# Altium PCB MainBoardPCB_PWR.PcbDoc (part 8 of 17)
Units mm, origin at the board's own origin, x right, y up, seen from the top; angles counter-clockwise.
Board outline 333.63 x 349.38 mm, 16 copper layers (L1, L2 (GND), L3 (Sign), L4 (GND), L5 (Sign), L6 (PWR/GND), L7(PWR/GND), L8 (PWR/GND), L9 (PWR/GND), L10 (PWR/GND), L11 (PWR/GND), L12 (Sign), L13 (GND), L14 (Sign), L15 (GND), L16), stack 2.503 mm thick; 2187 components, 1615 nets, 7987 pads, 1695 vias.
Unrouted connection lines stored in the file: 4757.
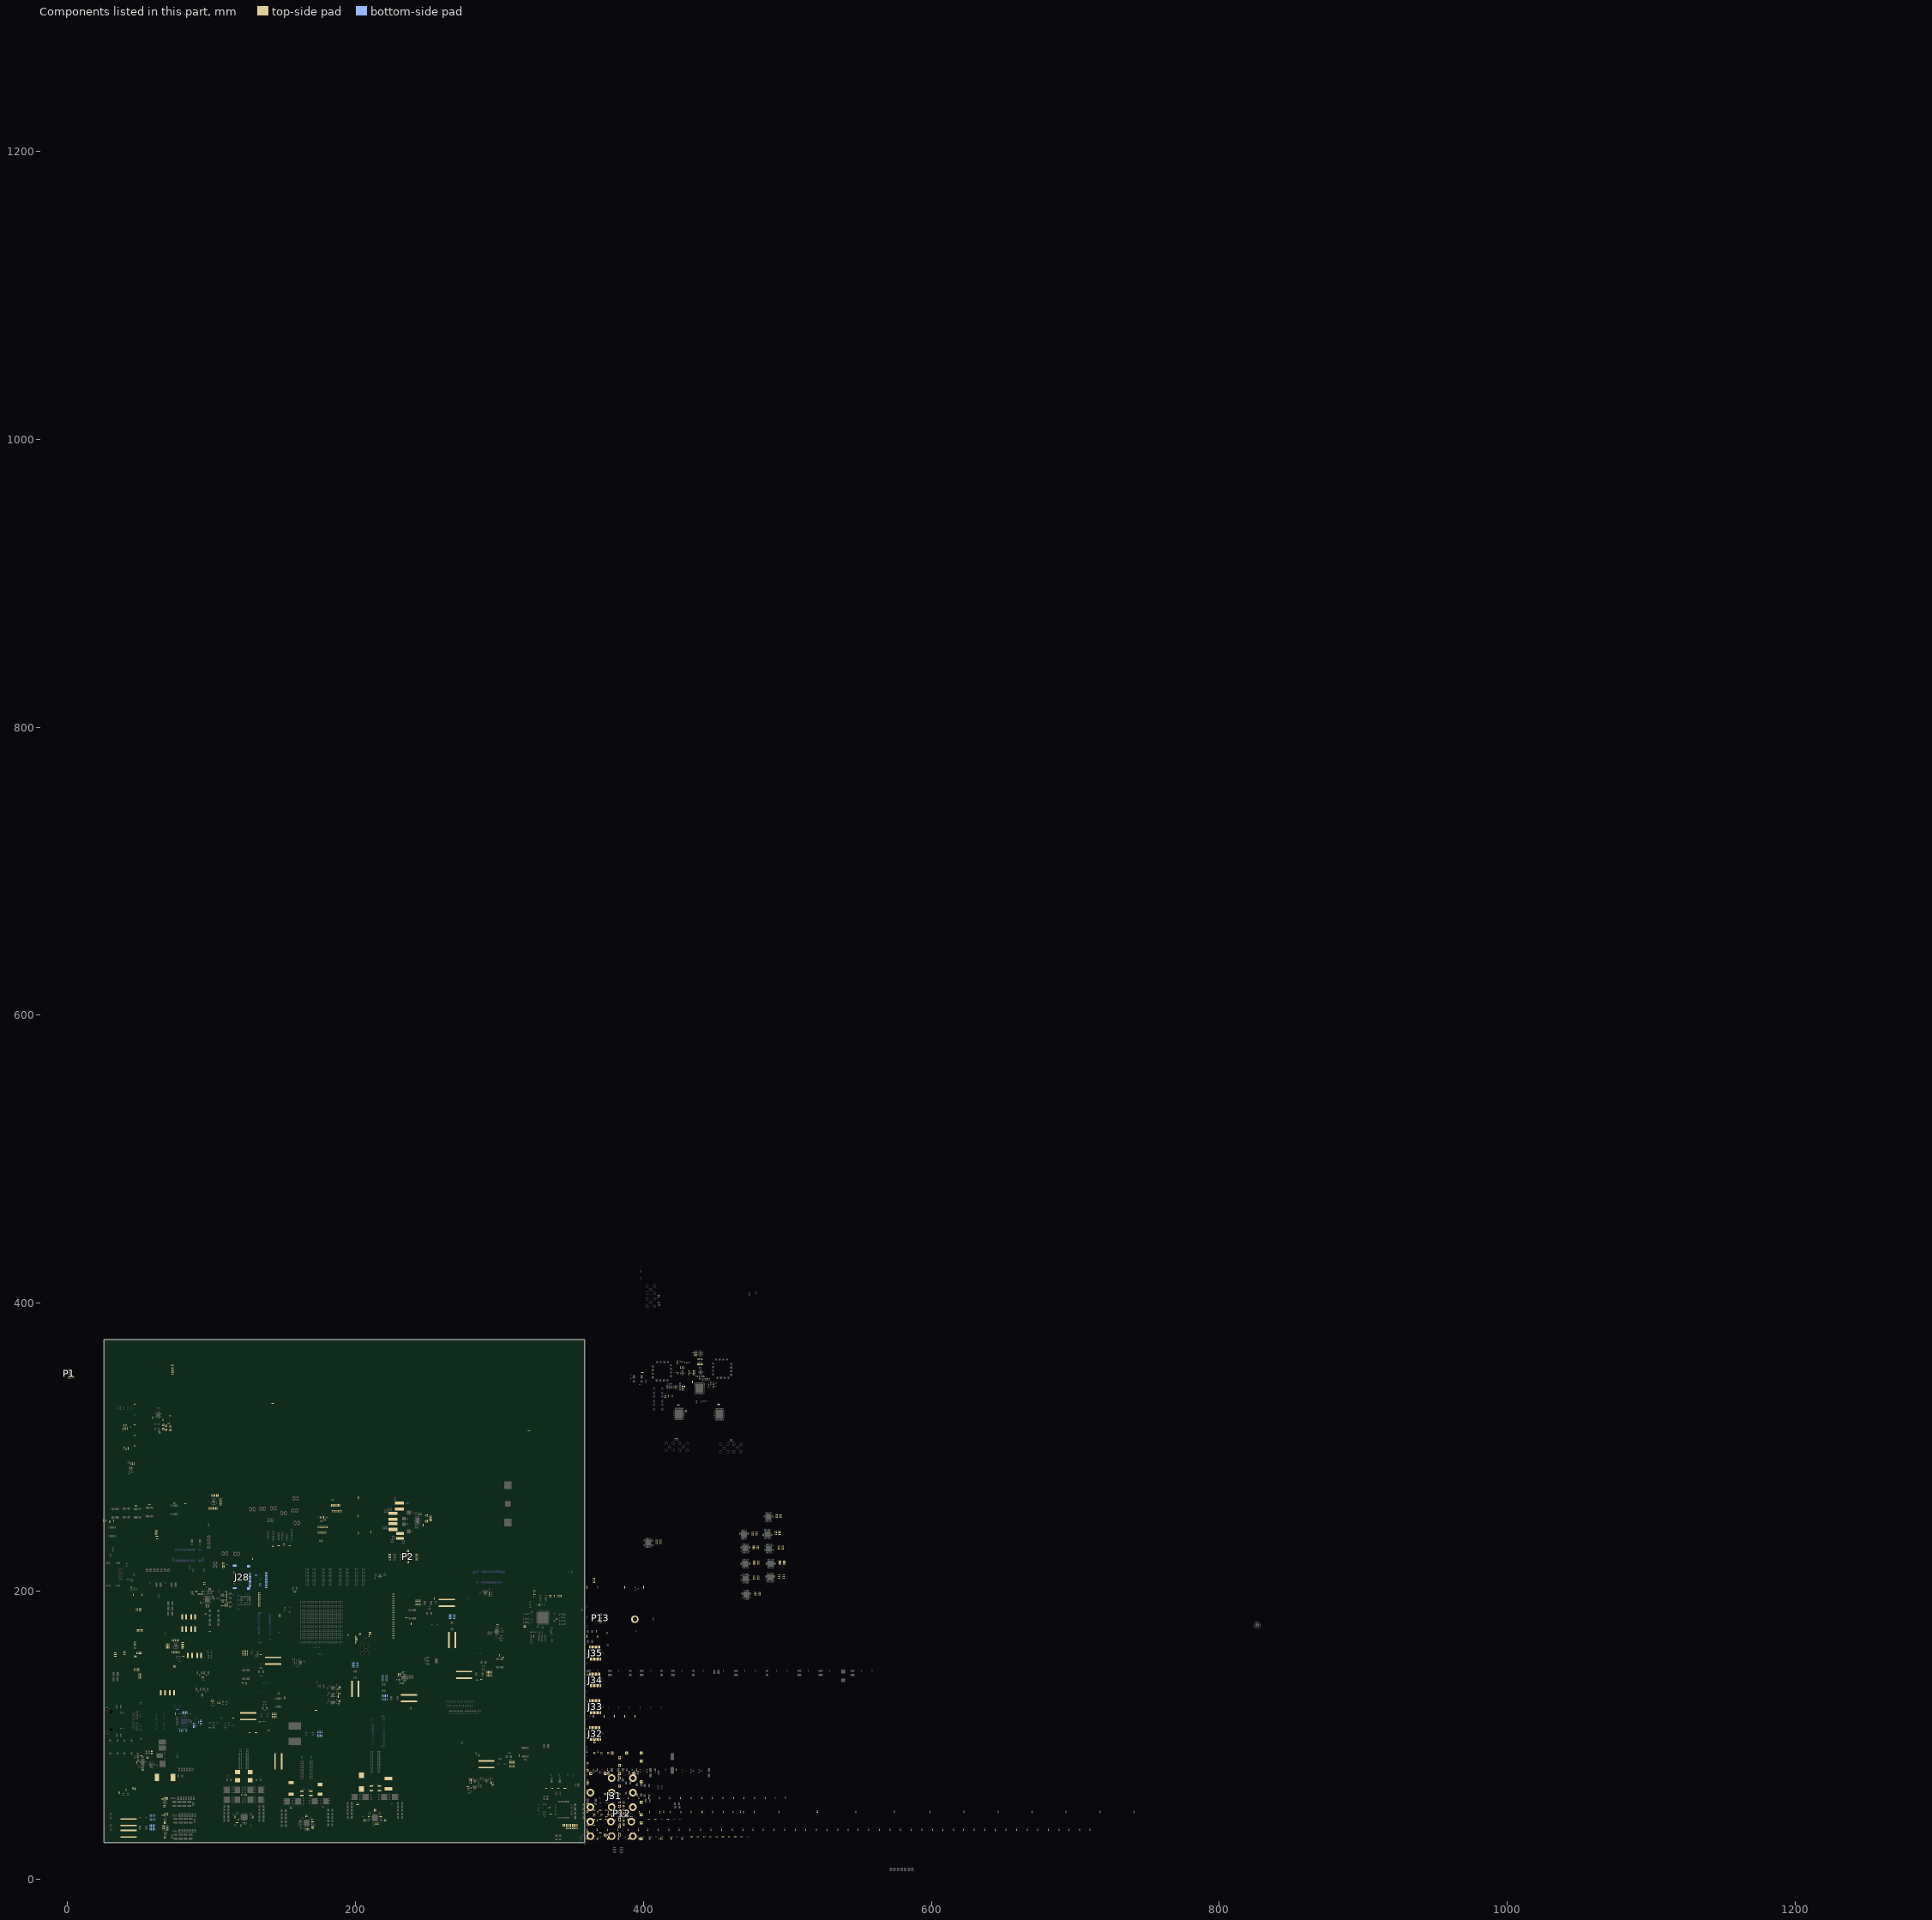
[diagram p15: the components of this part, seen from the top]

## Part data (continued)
J28: "WR-CRD Micro SD Card Connector Push & Push", Contact Resistance=100mOhm, Operating Temperature="-40 to +85degC", Rated Current=0.5A, Withstanding Voltage=500VAC, Working Voltage=30VAC
J31: library part 2007132, Flammability Rating="UL94 V-0", Manufacturer="TE Connectivity", Manufacturer Part Number=2007132-1, Package Quantity=16, Supplier Part Number 1=A97939-ND
J32 J33 J34 J35: "Conn zSFP+ F 20 POS 0.8mm Solder RA SMD 20 Terminal 1 Port zSFP+™ Reel", Current Rating=500mA, Flammability Rating="UL94 V-0", Housing Color=Black, Manufacturer=Molex, Max Operating Temperature=85°C, Max Voltage Rating (AC)=120V, Min Operating Temperature=-40°C, Package Quantity=960, Supplier Part Number 1=WM6178CT-ND
L1 L2 L3 L4 L5 L6 L7 L8: "Ind Power Shielded Wirewound 4.7uH 20% 100KHz Ferrite 1.7A Embossed T/R", Case/Package=Nonstandard, Current Rating=1.7A, DC Resistance (DCR)=84mR, Inductance=4.7uH, Manufacturer="Taiyo Yuden", Max Operating Temperature=125°C, Min Operating Temperature=-40°C, Package Quantity=3500, Ratings=AEC-Q200, Saturation Current=2A, Self Resonant Frequency=35MHz, Supplier Part Number 1=587-3578-1-ND, Test Frequency=100kHz, Tolerance=20%
L9 L10: "220nH Shielded Molded Inductor 25A 1.9mOhm Max Nonstandard", Inductance=220nH@25A, Manufacturer 1=Laird, Supplier Part Number 1=240-3179-1-ND
L11: "1.2µH Shielded Molded Inductor 17A 3.8mOhm Max Nonstandard", Inductance=1.2uH@17A, Manufacturer 1=Laird, Supplier Part Number 1=240-3187-1-ND
L12: "Wurth WE-LHMI Series Shielded Wire-wound SMD Inductor with a Iron Core, 0.68 µH Moulded 14A Idc", Case/Package=Nonstandard, Current Rating=14A, DC Resistance (DCR)=3.99mR, Inductance=680nH, Manufacturer 1="Wurth Electronics", Max Operating Temperature=125°C, Min Operating Temperature=-40°C, Saturation Current=32.5A, Self Resonant Frequency=53MHz, Supplier Part Number 1=732-7217-1-ND, Test Frequency=100kHz, Tolerance=20%
L13 L17: Inductance [µH]=8.2, Part Number=CDRH5D28NP-8R2
L15: library part Inductor, Manufacturer=TDK, Manufacturer Part Number=MLZ1608N6R8LT000, Supplier Part Number 1=445-MLZ1608N6R8LT000CT-ND
L16: Inductance="4.2 µH", Supplier Part Number 1=308-1802-1-ND
L18: "Fixed Inductors 3.3uH 1.57A 30% SMD LP INDUCTOR", Case/Package=Nonstandard, Current Rating=1.57A, DC Resistance (DCR)=49.2mR, Inductance=3.3uH, Manufacturer=Sumida, Max Operating Temperature=100°C, Min Operating Temperature=-40°C, Package Quantity=2000, Supplier Part Number 1=308-2184-1-ND, Test Frequency=100kHz, Tolerance=30%
L19: library part 7843330330, "WE-CHSA SMT High Current Inductor, size 1011, 3.3uH, 13.8A", DC Resistance max.=6.5mOhm, Inductance=3.3uH, Operating Temperature="-55 to +150degC", Rated Current=13.8A, Saturation Current=20.5A, Self Resonant Frequency=55MHz
L20: library part 7443340150, "SMT High Current Cube Inductor WE-HCC, size 8070, 1.5 uH, 16.5 A", DC Resistance max.="5.6 mOhm", Inductance="1.5 uH", Operating Temperature="-40 to +125 degC", Rated Current="16.5 A", Saturation Current="18.5 A", Self Resonant Frequency="120 MHz"
L22: "Inductor Power Shielded Wirewound 22uH 20% 100KHz 20Q-Factor Carbonyl Powder 9A 37mOhm DCR Automotive T/R", Case/Package=Nonstandard, Current Rating=9A, DC Resistance (DCR)=37mR, Inductance=22uH, Inductance Tolerance=20%, Manufacturer=Bourns, Max Operating Temperature=150°C, Min Operating Temperature=-40°C, Ratings=AEC-Q200, Saturation Current=12A, Self Resonant Frequency=6MHz, Supplier Part Number 1=SRP1265A-220MCT-ND, Test Frequency=100kHz
MP1_PCIE0 MP1_PCIE1 MP1_PCIE2 MP1_PCIE3 MP1_PCIE4 MP2_PCIE0 MP2_PCIE1 MP2_PCIE2 MP2_PCIE3 MP2_PCIE4 MP3_PCIE0 MP3_PCIE1 MP3_PCIE2 MP3_PCIE3 MP3_PCIE4: library part 9774025243R, "WA-SMSI SMT Steel Spacer, OD4.35mm, M2x2.5mm", Operating Temperature="-55 to +150degC"
P1 P13: "Header, 3-Pin"
P2: "Header, 4-Pin"
P3 P4 P5 P11: "Header, 2-Pin"
P6: "Male Header, Pitch 2.54 mm, 1 x 2 Position, Height 10.49 mm, Tail Length 3.556 mm, -55 to 105 degC, RoHS, Bulk", Color=White, Current, Rating="5  A", Flammability Rating=UL94V-0, Supplier Part Number 1=A1921-ND, Temperature, Operating="-55 to +105  °C", Voltage, Rating="250  V"
P12: "Header, 7-Pin, Dual row"
R1 R2 R71 R72 R73 R74 R91 R92 R93 R94 R127 R139 R141 R142 R143 R144 R151 R152 R153 R154 R161 R162 R163 R164 R345 R376 R377 R378 R402 R403 R404 R405 R406 R407 R408 R409 R411 R412 R413 R414 R415 R416 R418 R421 R481 R498 R540 R636 R637 R638 R639 R640 R641 R642 R643 R692 R722 R723 R724 R725 R726 R727 R728 R729: library part Resistor, "SMT Resistor", Case Code (Imperial)=0402, Case Code (Metric)=1005, Manufacturer=Vishay, Manufacturer Part Number=CRCW04020000Z0ED, Max Operating Temperature=155°C, Max Power Dissipation=63mW, Min Operating Temperature=-55°C, Package Quantity=1, Resistance=0mR, Supplier Part Number 1=541-0.0JCT-ND, Temperature Coefficient=100ppm/°C, Tolerance=5%, Voltage Rating=50V
R3_I2C_Bridge R3_I2C_Bridge_2 R3_I2C_Bridge_3 R4_I2C_Bridge R4_I2C_Bridge_2 R4_I2C_Bridge_3 R5_I2C_Bridge R5_I2C_Bridge_2 R5_I2C_Bridge_3 R6_I2C_Bridge R6_I2C_Bridge_2 R6_I2C_Bridge_3 R7_I2C_Bridge R7_I2C_Bridge_2 R7_I2C_Bridge_3 R8_I2C_Bridge R8_I2C_Bridge_2 R8_I2C_Bridge_3 R9_I2C_Bridge R9_I2C_Bridge_2 R9_I2C_Bridge_3 R10_I2C_Bridge R10_I2C_Bridge_2 R10_I2C_Bridge_3 R106 R109 R124 R223_I2C_Bridge R223_I2C_Bridge_2 R223_I2C_Bridge_3 R224_I2C_Bridge R224_I2C_Bridge_2 R224_I2C_Bridge_3 R225_I2C_Bridge R225_I2C_Bridge_2 R225_I2C_Bridge_3 R226_I2C_Bridge R226_I2C_Bridge_2 R226_I2C_Bridge_3 R227_I2C_Bridge R227_I2C_Bridge_2 R227_I2C_Bridge_3 R231_SPI_bridge2 R232_SPI_bridge1 R232_SPI_bridge2 R232_SPI_bridge3 R233_SPI_bridge2 R234_SPI_bridge1 R234_SPI_bridge2 R234_SPI_bridge3 R235_SPI_bridge1 R235_SPI_bridge2 R235_SPI_bridge3 R236_SPI_bridge2 R237_SPI_bridge1 R237_SPI_bridge2 R237_SPI_bridge3 R238_SPI_bridge2 R239_SPI_bridge1 R239_SPI_bridge2 R239_SPI_bridge3 R240_SPI_bridge2 R424 R428 R488 R499 R544 R558_I2C_Bridge R558_I2C_Bridge_2 R558_I2C_Bridge_3 R559_I2C_Bridge R559_I2C_Bridge_2 R559_I2C_Bridge_3 R560_I2C_Bridge R560_I2C_Bridge_2 R560_I2C_Bridge_3 R599 R694: library part Resistor, Case Code (Imperial)=0402, Case Code (Metric)=1005, Manufacturer=Panasonic, Manufacturer Part Number=ERJ-2RKF1001X, Max Operating Temperature=155°C, Max Power Dissipation=100mW, Min Operating Temperature=-55°C, Package Quantity=1, Supplier Part Number 1=P1.00KLCT-ND, Temperature Coefficient=100ppm/°C, Tolerance=1%, Voltage Rating=50V
R11 R13 R29 R30 R214 R218 R630: library part Resistor, Case/Package=0402, Case Code (Metric)=1005, Manufacturer 1=Yageo, Manufacturer Part Number 1=RC0402FR-0710KL, Max Operating Temperature=155°C, Min Operating Temperature=-55°C, Power Rating=62.5mW, Supplier Part Number 1=311-10.0KLRCT-ND, Temperature Coefficient=100ppm/°C, Tolerance=1%, Voltage Rating=50V
R12 R15 R17 R20 R677 R678 R679 R680: library part Resistor, Case/Package=0402, Case Code (Metric)=1005, Manufacturer 1=Yageo, Manufacturer Part Number 1=RC0402FR-0795K3L, Max Operating Temperature=155°C, Max Power Dissipation=63mW, Min Operating Temperature=-55°C, Package Quantity=1, Power Rating=62.5mW, Supplier Part Number 1=311-95.3KLRCT-ND, Temperature Coefficient=100ppm/°C, Tolerance=1%, Voltage Rating=50V
R14 R16 R22 R24 R304 R388 R389 R390 R665 R669 R670: library part Resistor, Case/Package=0402, Case Code (Metric)=1005, Manufacturer 1=Yageo, Manufacturer Part Number 1=RC0402JR-070RL, Max Operating Temperature=155°C, Max Power Dissipation=63mW, Min Operating Temperature=-55°C, Package Quantity=1, Power Rating=62.5mW, Supplier Part Number 1=311-0.0JRCT-ND, Temperature Coefficient=200ppm/°C, Tolerance=5%, Voltage Rating=50V
R18 R21 R681: library part Resistor, Case/Package=0402, Case Code (Metric)=1005, Manufacturer="Stackpole Electronics", Manufacturer Part Number=RMCF0402FT24K9, Max Operating Temperature=155°C, Max Power Dissipation=63mW, Min Operating Temperature=-55°C, Supplier Part Number 1=RMCF0402FT24K9CT-ND, Temperature Coefficient=100ppm/°C, Tolerance=1%
R19 R23 R25 R26 R683: library part Resistor, Case/Package=0402, Case Code (Metric)=1005, Manufacturer 1=Yageo, Manufacturer Part Number 1=RC0402FR-074K87L, Max Operating Temperature=155°C, Max Power Dissipation=63mW, Min Operating Temperature=-55°C, Power Rating=62.5mW, Supplier Part Number 1=YAG3175CT-ND, Temperature Coefficient=100ppm/°C, Tolerance=1%, Voltage Rating=50V
R27 R28 R182 R191 R200 R209 R228 R269: library part Resistor, Case/Package=0402, Case Code (Metric)=1005, Manufacturer=Panasonic, Manufacturer Part Number=ERJ-2RKF1021X, Max Operating Temperature=155°C, Max Power Dissipation=100mW, Min Operating Temperature=-55°C, Package Quantity=1, Supplier Part Number 1=P1.02KLCT-ND, Temperature Coefficient=100ppm/°C, Tolerance=1%, Voltage Rating=50V
R31 R32 R33 R34 R35 R36 R37 R38 R39 R40 R41 R42 R43 R44 R45 R46 R47 R48 R49 R50 R51 R53 R55 R57 R59: library part Resistor, Case/Package=0402, Case Code (Metric)=1005, Manufacturer=Panasonic, Manufacturer Part Number=ERJ-2RKF39R2X, Max Operating Temperature=155°C, Max Power Dissipation=100mW, Min Operating Temperature=-55°C, Package Quantity=1, Supplier Part Number 1=P39.2LCT-ND, Temperature Coefficient=100ppm/°C, Tolerance=1%, Voltage Rating=50V
R52 R54: library part Resistor, Case/Package=0402, Case Code (Metric)=1005, Manufacturer=Panasonic, Manufacturer Part Number=ERJ-2RKF36R0X, Max Operating Temperature=155°C, Max Power Dissipation=100mW, Min Operating Temperature=-55°C, Package Quantity=10000, Supplier Part Number 1=P36.0LCT-ND, Temperature Coefficient=100ppm/°C, Tolerance=1%, Voltage Rating=50V
R56: library part Resistor, Case/Package=0402, Case Code (Metric)=1005, Manufacturer=Yageo, Manufacturer Part Number=RC0402FR-07499RL, Max Operating Temperature=155°C, Max Power Dissipation=63mW, Min Operating Temperature=-55°C, Package Quantity=1, Power Rating=62.5mW, Supplier Part Number 1=311-499LRCT-ND, Temperature Coefficient=100ppm/°C, Tolerance=1%, Voltage Rating=50V
R58 R99: library part Resistor, Case/Package=0402, Case Code (Metric)=1005, Manufacturer=Panasonic, Manufacturer Part Number=ERJ-2RKF4701X, Max Operating Temperature=155°C, Max Power Dissipation=100mW, Min Operating Temperature=-55°C, Package Quantity=1, Supplier Part Number 1=P4.70KLCT-ND, Temperature Coefficient=100ppm/°C, Tolerance=1%, Voltage Rating=50V
R60 R231_SPI_bridge1 R231_SPI_bridge3 R233_SPI_bridge1 R233_SPI_bridge3 R236_SPI_bridge1 R236_SPI_bridge3 R238_SPI_bridge1 R238_SPI_bridge3 R240_SPI_bridge1 R240_SPI_bridge3 R252 R253 R254 R255 R427 R538: library part Resistor, Case/Package=0402, Case Code (Metric)=1005, Manufacturer=Panasonic, Manufacturer Part Number=ERJ-2RKF1001X, Max Operating Temperature=155°C, Max Power Dissipation=100mW, Min Operating Temperature=-55°C, Package Quantity=1, Supplier Part Number 1=P1.00KLCT-ND, Temperature Coefficient=100ppm/°C, Tolerance=1%, Voltage Rating=50V
R61 R62 R63 R64: library part Resistor, Case/Package=0402, Case Code (Metric)=1005, Manufacturer=Vishay, Manufacturer Part Number=CRCW0402240RFKED, Max Operating Temperature=155°C, Max Power Dissipation=63mW, Min Operating Temperature=-55°C, Package Quantity=10, Supplier Part Number 1=541-240LCT-ND, Temperature Coefficient=100ppm/°C, Tolerance=1%, Voltage Rating=50V
R65 R66 R67 R68 R83 R84 R85 R86 R97 R98 R123 R135 R136 R137 R138 R145 R146 R147 R148 R155 R156 R157 R158 R276 R346 R347 R348 R349 R350 R351 R352 R353 R354 R355 R356 R357 R363 R364 R365 R367 R381 R382 R425 R426 R730 R731 R732 R733 R734: library part Resistor, Case Code (Imperial)=0402, Case Code (Metric)=1005, Manufacturer=Panasonic, Manufacturer Part Number=ERJ-2RKF4701X, Max Operating Temperature=155°C, Max Power Dissipation=100mW, Min Operating Temperature=-55°C, Package Quantity=1, Supplier Part Number 1=P4.70KLCT-ND, Temperature Coefficient=100ppm/°C, Tolerance=1%, Voltage Rating=50V
R69 R70 R75 R76 R78 R79 R80 R82 R126 R311 R489 R534 R535 R541 R542 R543 R654 R657: library part Resistor, Case Code (Imperial)=0402, Case Code (Metric)=1005, Manufacturer="Vishay Dale", Manufacturer Part Number=CRCW0402100RFKED, Max Operating Temperature=155°C, Max Power Dissipation=63mW, Min Operating Temperature=-55°C, Package Quantity=10, Supplier Part Number 1=541-100LDKR-ND, Temperature Coefficient=100ppm/°C, Tolerance=1%, Voltage Rating=50V
R77: library part Resistor, "RES SMD 7.5K OHM 0.5% 1/16W 0402", Case Code (Imperial)=0402, Case Code (Metric)=1005, Manufacturer=Susumu, Manufacturer Part Number=RR0510P-752-D, Max Operating Temperature=125°C, Max Power Dissipation=63mW, Min Operating Temperature=-55°C, Package Quantity=1, Power Rating=62.5mW, Supplier Part Number 1=RR05P7.5KDCT-ND, Temperature Coefficient=25ppm/°C, Tolerance=0.5%, Voltage Rating=25V, Voltage Rating (DC)=50V
R81 R245 R305 R308 R309: library part Resistor, Case/Package=0402, Case Code (Metric)=1005, Manufacturer="Vishay Dale", Manufacturer Part Number=CRCW0402100RFKED, Max Operating Temperature=155°C, Max Power Dissipation=63mW, Min Operating Temperature=-55°C, Package Quantity=10, Supplier Part Number 1=541-100LDKR-ND, Temperature Coefficient=100ppm/°C, Tolerance=1%, Voltage Rating=50V
R87 R88 R89 R90 R95 R96 R101 R102 R103 R104 R105 R107 R108 R110 R111 R112 R115 R116 R117 R118 R119 R120 R121 R122 R362: library part Resistor, "RES SMD 30 OHM 0.5% 1/16W 0402", Case Code (Imperial)=0402, Case Code (Metric)=1005, Manufacturer=Panasonic, Manufacturer Part Number=ERA-2AKD300X, Max Operating Temperature=155°C, Max Power Dissipation=63mW, Min Operating Temperature=-55°C, Package Quantity=10000, Power Rating=62.5mW, Supplier Part Number 1=P30DDCT-ND, Temperature Coefficient=100ppm/°C, Tolerance=0.5%
R100 R292 R629: library part Resistor
R113: library part Resistor, "Thick Film Resistors 34.8K OHM 1%", Case Code (Imperial)=0402, Case Code (Metric)=1005, Manufacturer=Yageo, Manufacturer Part Number=RC0402FR-0734K8L, Max Operating Temperature=155°C, Max Power Dissipation=63mW, Min Operating Temperature=-55°C, Power Rating=62.5mW, Supplier Part Number 1=YAG3125CT-ND, Temperature Coefficient=100ppm/°C, Tolerance=1%, Voltage Rating=50V
R114 R274 R340 R343 R395 R398 R506 R507 R514 R515 R522 R523 R530 R531 R546 R547 R548 R549 R550 R551 R552 R553 R554 R555 R556 R557 R618 R659 R660 R661 R662 R663 R664 R688 R735 R744 R817 R818 R819 R820 R821 R822 R823 R824 R833 R834 R836 R837 R839: library part Resistor, Case Code (Imperial)=0402, Case Code (Metric)=1005, Manufacturer 1=Yageo, Manufacturer Part Number 1=RC0402FR-0710KL, Max Operating Temperature=155°C, Min Operating Temperature=-55°C, Power Rating=62.5mW, Supplier Part Number 1=311-10.0KLRCT-ND, Temperature Coefficient=100ppm/°C, Tolerance=1%, Voltage Rating=50V
R125 R128 R129: library part Resistor, "SMT Resistor", Case/Package=0402, Case Code (Metric)=1005, Manufacturer=Panasonic, Manufacturer Part Number=ERJ-2RKF1002X, Max Operating Temperature=155°C, Max Power Dissipation=100mW, Min Operating Temperature=-55°C, Package Quantity=1, Supplier Part Number 1=P10.0KLCT-ND, Temperature Coefficient=100ppm/°C, Tolerance=1%, Voltage Rating=50V
R130 R131 R132 R133 R134: library part Resistor, "SMT Resistor", Case/Package=0402, Case Code (Metric)=1005, Manufacturer=Vishay, Manufacturer Part Number=CRCW04020000Z0ED, Max Operating Temperature=155°C, Max Power Dissipation=63mW, Min Operating Temperature=-55°C, Package Quantity=1, Resistance=0mR, Supplier Part Number 1=541-0.0JCT-ND, Temperature Coefficient=100ppm/°C, Tolerance=5%, Voltage Rating=50V
R140: library part Resistor, "RES SMD 2.2 OHM 5% 1/16W 0402", Case Code (Imperial)=0402, Case Code (Metric)=1005, Manufacturer=Yageo, Manufacturer Part Number=RC0402JR-072R2L, Max Operating Temperature=155°C, Max Power Dissipation=63mW, Min Operating Temperature=-55°C, Package Quantity=1, Power Rating=62.5mW, Supplier Part Number 1=311-2.2JRCT-ND, Temperature Coefficient=200ppm/°C, Tolerance=5%, Voltage Rating=50V
R149: library part Resistor, "Thick Film Resistors - SMD 196K OHM 1%", Case/Package=0402, Case Code (Metric)=1005, Manufacturer=Yageo, Manufacturer Part Number=RC0402FR-07196KL, Max Operating Temperature=155°C, Max Power Dissipation=63mW, Min Operating Temperature=-55°C, Power Rating=62.5mW, Supplier Part Number 1=YAG3024CT-ND, Temperature Coefficient=100ppm/°C, Tolerance=1%, Voltage Rating=50V
R150: library part Resistor, "TE CONNECTIVITY - CRGCQ0402F22K - RES, 22K, 1%, 0402, THICK FILM", Manufacturer="TE Connectivity", Manufacturer Part Number=CRGCQ0402F22K, Supplier Part Number 1=A129643CT-ND
R159: library part Resistor, "Surface Mount Thick Film Resistor, Rc Series, 10 Kohm, 62.5 Mw, - 1%, 50 V, 0402 [1005 Metric]", Case/Package=0402, Case Code (Metric)=1005, Manufacturer=Yageo, Manufacturer Part Number=RC0402FR-0710KL, Max Operating Temperature=155°C, Min Operating Temperature=-55°C, Power Rating=62.5mW, Supplier Part Number 1=311-10.0KLRDKR-ND, Temperature Coefficient=100ppm/°C, Tolerance=1%, Voltage Rating=50V
R160: library part Resistor, "RES SMD 910 OHM 5% 1/10W 0402", Case Code (Imperial)=0402, Case Code (Metric)=1005, Manufacturer=Panasonic, Manufacturer Part Number=ERJ2GEJ911X, Max Operating Temperature=155°C, Max Power Dissipation=100mW, Min Operating Temperature=-55°C, Package Quantity=1, Supplier Part Number 1=P910JCT-ND, Temperature Coefficient=200ppm/°C, Tolerance=5%, Voltage Rating=50V
R165 R166 R167 R168 R169 R170 R171 R172 R321: library part Resistor, "RES SMD 100 OHM 1% 1/16W 0402", Case Code (Imperial)=0402, Case Code (Metric)=1005, Manufacturer=Yageo, Manufacturer Part Number=RC0402FR-07100RL, Max Operating Temperature=155°C, Min Operating Temperature=-55°C, Power Rating=62.5mW, Supplier Part Number 1=311-100LRDKR-ND, Temperature Coefficient=100ppm/°C, Tolerance=1%, Voltage Rating=50V
R173: library part Resistor, "RES SMD 500 OHM 0.1% 1/20W 0402", Case Code (Imperial)=0402, Case Code (Metric)=1005, Manufacturer="Vishay Dale", Manufacturer Part Number=PNM0402E5000BST1, Max Operating Temperature=155°C, Max Power Dissipation=50mW, Min Operating Temperature=-55°C, Package Quantity=1000, Supplier Part Number 1=541-1905-1-ND, Temperature Coefficient=25ppm/°C, Tolerance=0.1%
R174 R175 R176 R177 R178 R179 R180 R181 R183 R184 R185 R186 R187 R188 R189 R190 R192 R193 R194 R195 R196 R197 R198 R199 R201 R202 R203 R204 R205 R206 R207 R208 R210 R211 R213 R215 R217 R219 R221 R222 R229 R230 R241 R242 R243 R244 R264 R265 R279 R281 R282 R283 R286 R400 R449 R450 R451 R452 R453 R454 R455 R456 R457 R458 R459 R460 R461 R462 R463 R464 R465 R466 R467 R468 R469 R470 R471 R472 R473 R474 R475 R476 R477 R478 R479 R480 R492 R493 R494 R495 R496 R497 R500 R501 R502 R503 R504 R505 R508 R509 R510 R511 R512 R513 R516 R517 R518 R519 R520 R521 R524 R525 R526 R527 R528 R529 R561 R562 R563 R564 R565 R566 R567 R568 R569 R570 R571 R572 R573 R574 R575 R576 R577 R578 R579 R580 R581 R582 R583 R584 R585 R586 R587 R588 R589 R590 R591 R592 R593 R594 R595 R596 R597 R598 R607 R675 R693 R696 R697 R698 R699 R700 R701 R702 R703 R704 R705 R706 R707 R708 R711 R712 R713 R736 R738 R739 R740 R741 R742 R743 R758 R759 R760 R761 R762 R763 R765 R766 R767 R768 R769 R770 R771 R772 R773 R774 R775 R776 R777 R778 R779 R780 R781 R782 R783 R784 R785 R786 R787 R788 R789 R790 R791 R792 R793 R794 R795 R796 R797 R798 R799 R800 R801 R802 R803 R804 R805 R806 R807 R808 R809 R810 R811 R812 R813 R814 R815 R816: library part Resistor, Case Code (Imperial)=0402, Case Code (Metric)=1005, Manufacturer 1=Yageo, Manufacturer Part Number 1=RC0402JR-070RL, Max Operating Temperature=155°C, Max Power Dissipation=63mW, Min Operating Temperature=-55°C, Package Quantity=1, Power Rating=62.5mW, Supplier Part Number 1=311-0.0JRCT-ND, Temperature Coefficient=200ppm/°C, Tolerance=5%, Voltage Rating=50V
R212: library part Resistor, "SMT Resistor", Supplier Part Number 1=RR05P12.4KDCT-ND
R216: library part Resistor, Case/Package=0402, Manufacturer="Vishay Dale", Manufacturer Part Number=TNPW040231K2BEED, Max Operating Temperature=125°C, Max Power Dissipation=63mW, Min Operating Temperature=-55°C, Supplier Part Number 1=541-3564-1-ND, Temperature Coefficient=25ppm/°C, Tolerance=0.1%
R220: library part Resistor, Case Code (Imperial)=0402, Case Code (Metric)=1005, Manufacturer=Panasonic, Manufacturer Part Number=ERA-2AEB4991X, Max Operating Temperature=155°C, Max Power Dissipation=63mW, Min Operating Temperature=-55°C, Package Quantity=1, Power Rating=62.5mW, Supplier Part Number 1=P4.99KDCCT-ND, Temperature Coefficient=25ppm/°C, Tolerance=0.1%, Voltage Rating=50V
R246 R249 R256 R258: library part Resistor, "Res Thin Film 0402 120 Ohm 0.5% 1/16W ±25ppm/C Molded SMD Punched Carrier T/R", Case Code (Imperial)=0402, Case Code (Metric)=1005, Manufacturer=Panasonic, Manufacturer Part Number=ERA-2AED121X, Max Operating Temperature=155°C, Max Power Dissipation=63mW, Min Operating Temperature=-55°C, Package Quantity=10000, Supplier Part Number 1=P120DECT-ND, Temperature Coefficient=25ppm/°C, Tolerance=0.5%, Voltage Rating=25V
R247 R248 R261 R262: library part Resistor, "Res Thick Film 0402 127 Ohm 1% 0.063W(1/16W) �}100ppm/�? Molded SMD Paper T/R", Case Code (Imperial)=0402, Case Code (Metric)=1005, Manufacturer=Yageo, Manufacturer Part Number=RC0402FR-07127RL, Max Operating Temperature=155°C, Max Power Dissipation=63mW, Min Operating Temperature=-55°C, Power Rating=62.5mW, Supplier Part Number 1=YAG2963CT-ND, Temperature Coefficient=100ppm/°C, Tolerance=1%, Voltage Rating=50V
R250 R251 R259 R260: library part Resistor, "Res Thick Film 0402 82.5 Ohm 1% 0.063W(1/16W) ±100ppm/C Molded SMD Automotive Punched Paper T/R", Case Code (Imperial)=0402, Case Code (Metric)=1005, Manufacturer="KOA Speer", Manufacturer Part Number=RK73H1ETTP82R5F, Max Operating Temperature=155°C, Min Operating Temperature=-55°C, Package Quantity=10000, Power Rating=63mW, Supplier Part Number 1=2019-RK73H1ETTP82R5FCT-ND, Temperature Coefficient=100ppm/°C, Tolerance=1%, Voltage Rating=50V
R257 R545: library part Resistor, "RES SMD 49.9 OHM 1% 1/16W 0402", Case Code (Imperial)=0402, Case Code (Metric)=1005, Manufacturer=Yageo, Manufacturer Part Number=RC0402FR-0749R9L, Max Operating Temperature=155°C, Max Power Dissipation=63mW, Min Operating Temperature=-55°C, Package Quantity=1, Power Rating=62.5mW, Supplier Part Number 1=311-49.9LRDKR-ND, Temperature Coefficient=100ppm/°C, Tolerance=1%, Voltage Rating=50V
R263: library part Resistor, "RES 60.4K OHM 1% 1/16W 0402", Case Code (Imperial)=0402, Case Code (Metric)=1005, Manufacturer="Stackpole Electronics", Manufacturer Part Number=RMCF0402FT60K4, Max Operating Temperature=155°C, Max Power Dissipation=63mW, Min Operating Temperature=-55°C, Supplier Part Number 1=RMCF0402FT60K4CT-ND, Temperature Coefficient=100ppm/°C, Tolerance=1%
R266: library part Resistor, "Thick Film Resistors - SMD 84.5K OHM 1%", Case/Package=0402, Case Code (Metric)=1005, Manufacturer=Yageo, Manufacturer Part Number=RC0402FR-0784K5L, Max Operating Temperature=155°C, Max Power Dissipation=63mW, Min Operating Temperature=-55°C, Power Rating=62.5mW, Supplier Part Number 1=YAG3245CT-ND, Temperature Coefficient=100ppm/°C, Tolerance=1%, Voltage Rating=50V
R267: library part Resistor, "RES SMD 4.7K OHM 5% 1/16W 0402", Case/Package=0402, Case Code (Metric)=1005, Manufacturer=Yageo, Manufacturer Part Number=RC0402JR-074K7L, Max Operating Temperature=155°C, Max Power Dissipation=63mW, Min Operating Temperature=-55°C, Package Quantity=1, Supplier Part Number 1=311-4.7KJRCT-ND, Temperature Coefficient=100ppm/°C, Tolerance=5%, Voltage Rating=50V
R268 R272 R285 R289 R303 R307: library part Resistor, Case/Package=0402, Case Code (Metric)=1005, Manufacturer 1=Yageo, Manufacturer Part Number 1=RC0402FR-072RL, Max Operating Temperature=155°C, Max Power Dissipation=63mW, Min Operating Temperature=-55°C, Supplier Part Number 1=YAG3369CT-ND, Temperature Coefficient=200ppm/°C, Tolerance=1%, Voltage Rating=50V
R270 R539: library part Resistor, "Res Thick Film 0402 160 Ohm 1% 1/16W 100ppm/C Molded SMD SMD Paper T/R", Case/Package=0402, Manufacturer="Stackpole Electronics", Manufacturer Part Number=RMCF0402FT160R, Max Operating Temperature=155°C, Min Operating Temperature=-55°C, Supplier Part Number 1=RMCF0402FT160RCT-ND, Temperature Coefficient=100ppm/°C, Tolerance=1%
R271: library part Resistor, "RES SMD 5K OHM 0.1% 1/20W 0402", Case Code (Imperial)=0402, Case Code (Metric)=1005, Manufacturer="Vishay Dale", Manufacturer Part Number=PNM0402E5001BST1, Max Operating Temperature=155°C, Max Power Dissipation=50mW, Min Operating Temperature=-55°C, Package Quantity=1000, Supplier Part Number 1=541-1901-1-ND, Temperature Coefficient=25ppm/°C, Tolerance=0.1%
R273 R277 R278 R295 R296 R313 R314: library part Resistor, "CRGCQ 0402 12K 1%", Manufacturer="TE Connectivity", Manufacturer Part Number=CRGCQ0402F12K, Supplier Part Number 1=A129640CT-ND
R275 R280: library part Resistor, "RES SMD 47K OHM 1% 1/16W 0402", Case Code (Imperial)=0402, Case Code (Metric)=1005, Manufacturer=Yageo, Manufacturer Part Number=RC0402FR-0747KL, Max Operating Temperature=155°C, Max Power Dissipation=63mW, Min Operating Temperature=-55°C, Package Quantity=1, Power Rating=62.5mW, Supplier Part Number 1=311-47.0KLRCT-ND, Temperature Coefficient=100ppm/°C, Tolerance=1%, Voltage Rating=50V
R284: library part Resistor, "SMT Resistor", Supplier Part Number 1=RR05P18.2KDCT-ND
R287: library part Resistor, Case/Package=0402, Manufacturer="Stackpole Electronics", Manufacturer Part Number=RNCF0402DTE49K9, Max Operating Temperature=155°C, Min Operating Temperature=-55°C, Power Rating=63mW, Supplier Part Number 1=RNCF0402DTE49K9CT-ND, Tolerance=0.5%
R288 R298 R306 R316: "RES SMD 3.6 OHM 5% 1/2W 1210", Case Code (Imperial)=1210, Case Code (Metric)=3225, Manufacturer=Rohm, Manufacturer Part Number=ESR25JZPJ3R6, Max Operating Temperature=155°C, Max Power Dissipation=500mW, Min Operating Temperature=-55°C, Package Quantity=4000, Power="Power (Watts)", Resistance=3.6R, Supplier Part Number 1=RHM3.6AXCT-ND, Temperature Coefficient=200ppm/°C, Tolerance=5%
R290 R297 R300: library part Resistor, Case/Package=0402, Case Code (Metric)=1005, Manufacturer=Panasonic, Manufacturer Part Number=ERA-2AEB103X, Max Operating Temperature=155°C, Max Power Dissipation=63mW, Min Operating Temperature=-55°C, Package Quantity=1, Supplier Part Number 1=P10KDCCT-ND, Temperature Coefficient=25ppm/°C, Tolerance=0.1%, Voltage Rating=25V
R291 R301 R482 R483: library part Resistor, Case Code (Imperial)=0402, Case Code (Metric)=1005, Manufacturer=Yageo, Manufacturer Part Number=RC0402FR-07150RL, Max Operating Temperature=155°C, Max Power Dissipation=63mW, Min Operating Temperature=-55°C, Package Quantity=1, Power Rating=62.5mW, Supplier Part Number 1=311-150LRCT-ND, Temperature Coefficient=100ppm/°C, Tolerance=1%, Voltage Rating=50V
R293 R294 R310 R312: library part Resistor, Case/Package=0402, Case Code (Metric)=1005, Manufacturer=Multicomp, Manufacturer Part Number=MC0402WG00000TCE-TR, Power Rating=63mW, Supplier Part Number 1=1127362, Temperature Coefficient=200ppm/°C, Tolerance=1%, Voltage Rating=25V
R299 R317: library part Resistor, Case/Package=0402, Case Code (Metric)=1005, Manufacturer=Panasonic, Manufacturer Part Number=ERJ-2GEJ473X, Max Operating Temperature=155°C, Max Power Dissipation=100mW, Min Operating Temperature=-55°C, Package Quantity=1, Supplier Part Number 1=P47KJCT-ND, Temperature Coefficient=200ppm/°C, Tolerance=5%, Voltage Rating=50V
R302: library part Resistor, "Thick Film Resistors - SMD 1.4K OHM 1%", Case Code (Imperial)=0402, Case Code (Metric)=1005, Manufacturer=Yageo, Manufacturer Part Number=RC0402FR-071K4L, Max Operating Temperature=155°C, Max Power Dissipation=63mW, Min Operating Temperature=-55°C, Power Rating=62.5mW, Supplier Part Number 1=YAG3039CT-ND, Temperature Coefficient=100ppm/°C, Tolerance=1%, Voltage Rating=50V
R315: library part Resistor, "Thick Film Resistors - SMD 196K OHM 1%", Case Code (Imperial)=0402, Case Code (Metric)=1005, Manufacturer=Yageo, Manufacturer Part Number=RC0402FR-07196KL, Max Operating Temperature=155°C, Max Power Dissipation=63mW, Min Operating Temperature=-55°C, Power Rating=62.5mW, Supplier Part Number 1=YAG3024CT-ND, Temperature Coefficient=100ppm/°C, Tolerance=1%, Voltage Rating=50V
R318: library part Resistor, "RES 27K OHM 1% 1/16W 0402", Case Code (Imperial)=0402, Case Code (Metric)=1005, Manufacturer="Stackpole Electronics", Manufacturer Part Number=RMCF0402FT27K0, Max Operating Temperature=155°C, Max Power Dissipation=63mW, Min Operating Temperature=-55°C, Package Quantity=10000, Power Rating=62.5mW, Supplier Part Number 1=RMCF0402FT27K0CT-ND, Temperature Coefficient=100ppm/°C, Tolerance=1%
R319 R320 R490 R710 R715: library part Resistor, Case Code (Imperial)=0402, Case Code (Metric)=1005, Manufacturer=Panasonic, Manufacturer Part Number=ERJ-2RKF1002X, Max Operating Temperature=155°C, Max Power Dissipation=100mW, Min Operating Temperature=-55°C, Package Quantity=1, Supplier Part Number 1=P10.0KLDKR-ND, Temperature Coefficient=100ppm/°C, Tolerance=1%, Voltage Rating=50V
R322 R323: library part Resistor, Case Code (Imperial)=0402, Case Code (Metric)=1005, Manufacturer="Stackpole Electronics", Manufacturer Part Number=RMCF0402FT5K76, Max Operating Temperature=155°C, Max Power Dissipation=63mW, Min Operating Temperature=-55°C, Supplier Part Number 1=RMCF0402FT5K76CT-ND, Temperature Coefficient=100ppm/°C, Tolerance=1%
R324: library part Resistor, "RES SMD 100K OHM 1% 1/8W 0805", Case/Package=0805, Case Code (Metric)=2012, Manufacturer=Yageo, Manufacturer Part Number=RC0805FR-07100KL, Max Operating Temperature=155°C, Max Power Dissipation=125mW, Min Operating Temperature=-55°C, Package Quantity=1, Supplier Part Number 1=311-100KCRDKR-ND, Temperature Coefficient=100ppm/°C, Tolerance=1%, Voltage Rating=150V
R325 R326 R327 R328: library part Resistor, Case Code (Imperial)=0402, Case Code (Metric)=1005, Manufacturer="Stackpole Electronics", Manufacturer Part Number=RMCF0402FT2K49, Max Operating Temperature=155°C, Max Power Dissipation=63mW, Min Operating Temperature=-55°C, Package Quantity=10000, Supplier Part Number 1=RMCF0402FT2K49CT-ND, Temperature Coefficient=100ppm/°C, Tolerance=1%
R329 R330 R331 R332: library part Resistor, "RES SMD 100 OHM 1% 1/16W 0402", Case/Package=0402, Case Code (Metric)=1005, Manufacturer=Yageo, Manufacturer Part Number=RC0402FR-07100RL, Max Operating Temperature=155°C, Min Operating Temperature=-55°C, Power Rating=62.5mW, Supplier Part Number 1=311-100LRDKR-ND, Temperature Coefficient=100ppm/°C, Tolerance=1%, Voltage Rating=50V
R333 R336 R337 R338 R709 R714: library part Resistor, "RES SMD 2.2K OHM 1% 1/16W 0402", Case Code (Imperial)=0402, Case Code (Metric)=1005, Manufacturer=Yageo, Manufacturer Part Number=RC0402FR-072K2L, Max Operating Temperature=155°C, Min Operating Temperature=-55°C, Power Rating=63mW, Supplier Part Number 1=311-2.20KLRCT-ND, Temperature Coefficient=100ppm/°C, Tolerance=1%, Voltage Rating=50V
R334: library part Resistor, Case/Package=0402, Case Code (Metric)=1005, Manufacturer 1=Yageo, Manufacturer Part Number 1=RC0402FR-0711KL, Max Operating Temperature=155°C, Max Power Dissipation=63mW, Min Operating Temperature=-55°C, Package Quantity=1, Supplier Part Number 1=311-11.0KLRCT-ND, Temperature Coefficient=100ppm/°C, Tolerance=1%, Voltage Rating=50V
R335: library part Resistor, "RES SMD 1M OHM 1% 1/16W 0402", Case/Package=0402, Case Code (Metric)=1005, Manufacturer=Vishay, Manufacturer Part Number=CRCW04021M00FKED, Max Operating Temperature=155°C, Max Power Dissipation=63mW, Min Operating Temperature=-55°C, Package Quantity=10, Supplier Part Number 1=541-1.00MLCT-ND, Temperature Coefficient=100ppm/°C, Tolerance=1%, Voltage Rating=50V
R339 R342 R430_5V_to_3V3_for_FTDI R430_U_5V_to_3V31 R430_U_5V_to_3V32 R430_U_5V_to_3V33: library part Resistor, "Thick Film Resistors - SMD 105K OHM 1%", Case Code (Imperial)=0402, Case Code (Metric)=1005, Manufacturer=Yageo, Manufacturer Part Number=RC0402FR-07105KL, Max Operating Temperature=155°C, Max Power Dissipation=63mW, Min Operating Temperature=-55°C, Power Rating=62.5mW, Supplier Part Number 1=YAG2946CT-ND, Temperature Coefficient=100ppm/°C, Tolerance=1%, Voltage Rating=50V
R341 R344 R432_5V_to_3V3_for_FTDI R432_U_5V_to_3V31 R432_U_5V_to_3V32 R432_U_5V_to_3V33: library part Resistor, "RES 15K OHM 1% 1/16W 0402", Case Code (Imperial)=0402, Case Code (Metric)=1005, Manufacturer="Stackpole Electronics", Manufacturer Part Number=RMCF0402FT15K0, Max Operating Temperature=155°C, Max Power Dissipation=63mW, Min Operating Temperature=-55°C, Supplier Part Number 1=RMCF0402FT15K0CT-ND, Temperature Coefficient=100ppm/°C, Tolerance=1%
R358 R359 R360 R361: library part Resistor, "Resistor;  Thick Film;  Res 499 Ohms;  Pwr-Rtg 0.1 W;  Tol 1%;  SMT;  0402;  Tape & Reel", Case Code (Imperial)=0402, Case Code (Metric)=1005, Manufacturer=Panasonic, Manufacturer Part Number=ERJ-2RKF4990X, Max Operating Temperature=155°C, Max Power Dissipation=100mW, Min Operating Temperature=-55°C, Package Quantity=1, Supplier Part Number 1=P499LCT-ND, Temperature Coefficient=100ppm/°C, Tolerance=1%, Voltage Rating=50V
R366 R369 R370 R371 R373: library part Resistor, "SMT Resistor", Case Code (Imperial)=0402, Case Code (Metric)=1005, Manufacturer=Panasonic, Manufacturer Part Number=ERJ-2RKF1002X, Max Operating Temperature=155°C, Max Power Dissipation=100mW, Min Operating Temperature=-55°C, Package Quantity=1, Supplier Part Number 1=P10.0KLCT-ND, Temperature Coefficient=100ppm/°C, Tolerance=1%, Voltage Rating=50V
R368 R716 R717 R718 R719 R720: library part Resistor, "Thick Film Resistors 0402 261ohms 1% AEC-Q200", Case Code (Imperial)=0402, Case Code (Metric)=1005, Manufacturer=Panasonic, Manufacturer Part Number=ERJ-2RKF2610X, Max Operating Temperature=155°C, Max Power Dissipation=100mW, Min Operating Temperature=-55°C, Package Quantity=1, Supplier Part Number 1=P261LCT-ND, Temperature Coefficient=100ppm/°C, Tolerance=1%, Voltage Rating=50V
R372 R379: library part Resistor, "RES 8.06K OHM 1% 1/16W 0402", Case Code (Imperial)=0402, Case Code (Metric)=1005, Manufacturer="Stackpole Electronics", Manufacturer Part Number=RMCF0402FT8K06, Max Operating Temperature=155°C, Max Power Dissipation=63mW, Min Operating Temperature=-55°C, Supplier Part Number 1=RMCF0402FT8K06CT-ND, Temperature Coefficient=100ppm/°C, Tolerance=1%
R374: library part Resistor, "Thick Film Resistors 0.1W 4.7Mohms 5%", Case Code (Imperial)=0402, Case Code (Metric)=1005, Manufacturer="KOA Speer", Manufacturer Part Number=RK73B1ETTP475J, Max Operating Temperature=155°C, Min Operating Temperature=-55°C, Package Quantity=10000, Power Rating=63mW, Supplier Part Number 1=2019-RK73B1ETTP475JCT-ND, Temperature Coefficient=200ppm/°C, Tolerance=5%, Voltage Rating=50V
R375: library part Resistor, "RES SMD 40.2 OHM 1% 1/16W 0402", Case Code (Imperial)=0402, Case Code (Metric)=1005, Manufacturer=Yageo, Manufacturer Part Number=RC0402FR-0740R2L, Max Operating Temperature=155°C, Max Power Dissipation=63mW, Min Operating Temperature=-55°C, Package Quantity=1, Power Rating=62.5mW, Supplier Part Number 1=311-40.2LRCT-ND, Temperature Coefficient=100ppm/°C, Tolerance=1%, Voltage Rating=50V
R380: library part Resistor, "Thick Film Resistors 4.22K OHM 1%", Case Code (Imperial)=0402, Case Code (Metric)=1005, Manufacturer=Yageo, Manufacturer Part Number=RC0402FR-074K22L, Max Operating Temperature=155°C, Max Power Dissipation=63mW, Min Operating Temperature=-55°C, Power Rating=62.5mW, Supplier Part Number 1=YAG3172CT-ND, Temperature Coefficient=100ppm/°C, Tolerance=1%, Voltage Rating=50V
R383: library part Resistor, Case Code (Imperial)=0402, Case Code (Metric)=1005, Manufacturer=Panasonic, Manufacturer Part Number=ERA-2AEB103X, Max Operating Temperature=155°C, Max Power Dissipation=63mW, Min Operating Temperature=-55°C, Package Quantity=1, Supplier Part Number 1=P10KDCCT-ND, Temperature Coefficient=25ppm/°C, Tolerance=0.1%, Voltage Rating=25V
R384 R385 R484 R485: library part Resistor, Case Code (Imperial)=0402, Case Code (Metric)=1005, Manufacturer=Vishay, Manufacturer Part Number=CRCW040271R5FKED, Max Operating Temperature=155°C, Max Power Dissipation=63mW, Min Operating Temperature=-55°C, Package Quantity=10, Supplier Part Number 1=541-71.5LCT-ND, Temperature Coefficient=100ppm/°C, Tolerance=1%, Voltage Rating=50V
R386 R486: library part Resistor, Case Code (Imperial)=0402, Case Code (Metric)=1005, Manufacturer="Stackpole Electronics", Manufacturer Part Number=RMCF0402FT8K87, Max Operating Temperature=155°C, Max Power Dissipation=63mW, Min Operating Temperature=-55°C, Package Quantity=1, Supplier Part Number 1=RMCF0402FT8K87CT-ND, Temperature Coefficient=100ppm/°C, Tolerance=1%
R387 R487: library part Resistor, Case Code (Imperial)=0402, Case Code (Metric)=1005, Manufacturer=Panasonic, Manufacturer Part Number=ERJ-2RKF5101X, Max Operating Temperature=155°C, Max Power Dissipation=100mW, Min Operating Temperature=-55°C, Package Quantity=10000, Supplier Part Number 1=P5.10KLCT-ND, Temperature Coefficient=100ppm/°C, Tolerance=1%, Voltage Rating=50V
R391: library part Resistor, "RES SMD 75K OHM 1% 1/16W 0402", Case/Package=0402, Case Code (Metric)=1005, Manufacturer=Yageo, Manufacturer Part Number=RC0402FR-0775KL, Max Operating Temperature=155°C, Max Power Dissipation=63mW, Min Operating Temperature=-55°C, Package Quantity=1, Power Rating=62.5mW, Supplier Part Number 1=311-75KLRCT-ND, Temperature Coefficient=100ppm/°C, Tolerance=1%, Voltage Rating=50V
R392 R431_5V_to_3V3_for_FTDI R431_U_5V_to_3V31 R431_U_5V_to_3V32 R431_U_5V_to_3V33 R442 R832 R835: library part Resistor, Case Code (Imperial)=0402, Case Code (Metric)=1005, Manufacturer 1=Panasonic, Manufacturer Part Number 1=ERA-2AED104X, Max Operating Temperature=155°C, Max Power Dissipation=63mW, Min Operating Temperature=-55°C, Package Quantity=10000, Supplier Part Number 1=P100KDECT-ND, Temperature Coefficient=25ppm/°C, Tolerance=0.5%, Voltage Rating=25V
R393 R396 R399: library part Resistor, "RES 15K OHM 1% 1/16W 0402", Case/Package=0402, Case Code (Metric)=1005, Manufacturer="Stackpole Electronics", Manufacturer Part Number=RMCF0402FT15K0, Max Operating Temperature=155°C, Max Power Dissipation=63mW, Min Operating Temperature=-55°C, Supplier Part Number 1=RMCF0402FT15K0CT-ND, Temperature Coefficient=100ppm/°C, Tolerance=1%
R394: library part Resistor, "RES 51.1K OHM 1% 1/16W 0402", Case/Package=0402, Case Code (Metric)=1005, Manufacturer="Stackpole Electronics", Manufacturer Part Number=RMCF0402FT51K1, Max Operating Temperature=155°C, Max Power Dissipation=63mW, Min Operating Temperature=-55°C, Supplier Part Number 1=RMCF0402FT51K1CT-ND, Temperature Coefficient=100ppm/°C, Tolerance=1%
R397: library part Resistor, "RES 21.5K OHM 1% 1/16W 0402", Case/Package=0402, Case Code (Metric)=1005, Manufacturer="Stackpole Electronics", Manufacturer Part Number=RMCF0402FT21K5, Max Operating Temperature=155°C, Max Power Dissipation=63mW, Min Operating Temperature=-55°C, Package Quantity=10000, Supplier Part Number 1=RMCF0402FT21K5CT-ND, Temperature Coefficient=100ppm/°C, Tolerance=1%
R401 R410 R417 R420 R422 R635 R721: library part Resistor, "SMT Resistor", Supplier Part Number 1=RR05P10.0KDCT-ND
R419: library part Resistor, "RES SMD 2K OHM 1% 1/16W 0402", Case Code (Imperial)=0402, Case Code (Metric)=1005, Manufacturer=Yageo, Manufacturer Part Number=RC0402FR-072KL, Max Operating Temperature=155°C, Max Power Dissipation=63mW, Min Operating Temperature=-55°C, Package Quantity=1, Supplier Part Number 1=311-2KLRDKR-ND, Temperature Coefficient=100ppm/°C, Tolerance=1%, Voltage Rating=50V
R423: library part Resistor, "RES SMD 12K OHM 1% 1/16W 0402", Case Code (Imperial)=0402, Case Code (Metric)=1005, Manufacturer=Yageo, Manufacturer Part Number=RC0402FR-0712KL, Max Operating Temperature=155°C, Max Power Dissipation=63mW, Min Operating Temperature=-55°C, Package Quantity=1, Power Rating=62.5mW, Supplier Part Number 1=311-12.0KLRCT-ND, Temperature Coefficient=100ppm/°C, Tolerance=1%, Voltage Rating=50V
R429: library part Resistor, Case/Package=0402, Case Code (Metric)=1005, Manufacturer=Yageo, Manufacturer Part Number=RC0402JR-070RL, Max Operating Temperature=155°C, Max Power Dissipation=63mW, Min Operating Temperature=-55°C, Package Quantity=1, Power Rating=62.5mW, Supplier Part Number 1=311-0.0JRCT-ND, Temperature Coefficient=200ppm/°C, Tolerance=5%, Voltage Rating=50V
R433: library part Resistor, "RES 56K OHM 1% 1/16W 0402", Case Code (Imperial)=0402, Case Code (Metric)=1005, Manufacturer="Stackpole Electronics", Manufacturer Part Number=RMCF0402FT56K0, Max Operating Temperature=155°C, Max Power Dissipation=63mW, Min Operating Temperature=-55°C, Package Quantity=10000, Supplier Part Number 1=RMCF0402FT56K0CT-ND, Temperature Coefficient=100ppm/°C, Tolerance=1%
R434 R649 R651 R655 R656 R658: library part Resistor, "RES 10K OHM 0.1% 1/16W 0402", Case Code (Imperial)=0402, Case Code (Metric)=1005, Manufacturer="Stackpole Electronics", Manufacturer Part Number=RNCF0402BTE10K0, Max Operating Temperature=155°C, Max Power Dissipation=63mW, Min Operating Temperature=-55°C, Package Quantity=10000, Supplier Part Number 1=RNCF0402BTE10K0CT-ND, Temperature Coefficient=25ppm/°C, Tolerance=0.1%
R435: library part Resistor, Case Code (Imperial)=0402, Case Code (Metric)=1005, Manufacturer=Yageo, Manufacturer Part Number=RC0402FR-0710KL, Max Operating Temperature=155°C, Min Operating Temperature=-55°C, Power Rating=62.5mW, Supplier Part Number 1=311-10.0KLRDKR-ND, Temperature Coefficient=100ppm/°C, Tolerance=1%, Voltage Rating=50V
R436 R438: library part Resistor, "Thick Film Resistors - SMD 3.57K OHM 1%", Case Code (Imperial)=0402, Case Code (Metric)=1005, Manufacturer=Yageo, Manufacturer Part Number=RC0402FR-073K57L, Max Operating Temperature=155°C, Max Power Dissipation=63mW, Min Operating Temperature=-55°C, Power Rating=62.5mW, Supplier Part Number 1=YAG3150CT-ND, Temperature Coefficient=100ppm/°C, Tolerance=1%, Voltage Rating=50V
R437 R439: library part Resistor, "Res General Purpose Thick Film 0402 1.15K Ohm 1% 1/16W ±100ppm/°C Molded SMD Paper T/R", Case Code (Imperial)=0402, Case Code (Metric)=1005, Manufacturer=Yageo, Manufacturer Part Number=RC0402FR-071K15L, Max Operating Temperature=155°C, Max Power Dissipation=63mW, Min Operating Temperature=-55°C, Power Rating=62.5mW, Supplier Part Number 1=YAG3033CT-ND, Temperature Coefficient=100ppm/°C, Tolerance=1%, Voltage Rating=50V
R440 R441 R668 R745: library part Resistor, "RES SMD 20K OHM 1% 1/16W 0402", Case Code (Imperial)=0402, Case Code (Metric)=1005, Manufacturer=Vishay, Manufacturer Part Number=CRCW040220K0FKED, Max Operating Temperature=155°C, Max Power Dissipation=63mW, Min Operating Temperature=-55°C, Package Quantity=10, Supplier Part Number 1=51X8496, Temperature Coefficient=100ppm/°C, Tolerance=1%, Voltage Rating=50V
R443: library part Resistor, "Panasonic ERA Series Thin Film Surface Mount Fixed Resistor 0805 Case 698k 0.1% 0.125W 25ppm/C", Case Code (Imperial)=0805, Case Code (Metric)=2012, Manufacturer=Panasonic, Manufacturer Part Number=ERA-6AEB6983V, Max Operating Temperature=155°C, Max Power Dissipation=125mW, Min Operating Temperature=-55°C, Package Quantity=5000, Supplier Part Number 1=P698KDACT-ND, Temperature Coefficient=25ppm/°C, Tolerance=0.1%, Voltage Rating=100V
R444 R445: library part Resistor, "Res Thin Film 0402 49.9K Ohm 0.1% 1/16W 25ppm/C Molded SMD SMD Punched Carrier T/R", Case Code (Imperial)=0402, Case Code (Metric)=1005, Manufacturer=Panasonic, Manufacturer Part Number=ERA-2AEB4992X, Max Operating Temperature=155°C, Max Power Dissipation=63mW, Min Operating Temperature=-55°C, Package Quantity=1, Power Rating=62.5mW, Supplier Part Number 1=P49.9KDCCT-ND, Temperature Coefficient=25ppm/°C, Tolerance=0.1%, Voltage Rating=50V
R446 R447: library part Resistor, "RES SMD 120 OHM 1% 1/16W 0402", Case Code (Imperial)=0402, Case Code (Metric)=1005, Manufacturer=Vishay, Manufacturer Part Number=CRCW0402120RFKED, Max Operating Temperature=155°C, Max Power Dissipation=63mW, Min Operating Temperature=-55°C, Package Quantity=10000, Supplier Part Number 1=541-120LCT-ND, Temperature Coefficient=100ppm/°C, Tolerance=1%, Voltage Rating=50V
R448_U_Pomiar_pradu_napiecia_1 R448_U_Pomiar_pradu_napiecia_2 R448_U_Pomiar_pradu_napiecia_3 R448_U_Pomiar_pradu_napiecia_4 R448_U_Pomiar_pradu_napiecia_5 R448_U_Pomiar_pradu_napiecia_6 R448_U_Pomiar_pradu_napiecia_7 R448_U_Pomiar_pradu_napiecia_8 R448_U_Pomiar_pradu_napiecia_9 R448_U_Pomiar_pradu_napiecia_10 R448_U_Pomiar_pradu_napiecia_11: "RES SMD 5 MOHM 5W 4320 WIDE", Case/Package=Metal, Manufacturer=Ohmite, Max Operating Temperature=155°C, Max Power Dissipation=5W, Min Operating Temperature=-55°C, Package Quantity=1, Resistance=5mR, Supplier Part Number 1=FCSL110R005FERCT-ND, Temperature Coefficient=50ppm/°C, Tolerance=1%
R491: library part Resistor, Case Code (Imperial)=0402, Case Code (Metric)=1005, Manufacturer=Panasonic, Manufacturer Part Number=ERJ-2GEJ105X, Max Operating Temperature=155°C, Max Power Dissipation=100mW, Min Operating Temperature=-55°C, Package Quantity=1, Supplier Part Number 1=P1.0MJCT-ND, Temperature Coefficient=200ppm/°C, Tolerance=5%, Voltage Rating=50V
R532: library part Resistor, "Res Thick Film 0402 75 Ohm 1% 1/10W 100ppm/C Molded SMD SMD Punched Carrier T/R", Case Code (Imperial)=0402, Case Code (Metric)=1005, Manufacturer=Panasonic, Manufacturer Part Number=ERJ-2RKF75R0X, Max Operating Temperature=155°C, Max Power Dissipation=100mW, Min Operating Temperature=-55°C, Package Quantity=1, Supplier Part Number 1=P75.0LDKR-ND, Temperature Coefficient=100ppm/°C, Tolerance=1%, Voltage Rating=50V
R533: library part Resistor, "RES 30 OHM 1% 1/16W 0402", Case/Package=0402, Manufacturer="Stackpole Electronics", Manufacturer Part Number=RMCF0402FT30R0, Max Operating Temperature=155°C, Min Operating Temperature=-55°C, Supplier Part Number 1=RMCF0402FT30R0CT-ND, Temperature Coefficient=100ppm/°C, Tolerance=1%
R536 R537: library part Resistor, "RES SMD 150 OHM 1% 1/10W 0402", Case Code (Imperial)=0402, Case Code (Metric)=1005, Manufacturer=Panasonic, Manufacturer Part Number=ERJ-2RKF1500X, Max Operating Temperature=155°C, Max Power Dissipation=100mW, Min Operating Temperature=-55°C, Package Quantity=1, Supplier Part Number 1=P150LCT-ND, Temperature Coefficient=100ppm/°C, Tolerance=1%, Voltage Rating=50V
